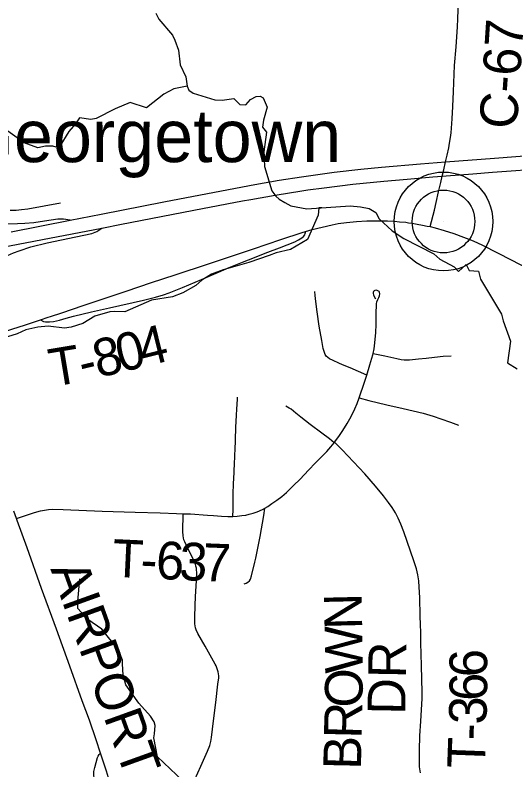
# Model space of a CAD drawing. Extents: x 0 to 34, y 0 to 22.
# Drawn here: x 6.555 to 7.308, y 16.504 to 17.641 of the extents above; entities that cross this region are included whole.
import ezdxf

# ---------------------------------------------------------------- set-up
doc = ezdxf.new("R2010")
doc.units = 0
for name, color, linetype in [('GM_X_County_Road', 7, 'Continuous'), ('GM_X_County_Road_Text', 7, 'Continuous'), ('GM_X_Interchange_Ramps', 7, 'Continuous'), ('GM_X_Interstate_Route', 7, 'Continuous'), ('GM_X_Minor_River', 7, 'Continuous'), ('GM_X_Township_Road', 7, 'Continuous'), ('GM_X_Township_Road_Text', 7, 'Continuous'), ('GM_X_Unincorporated', 7, 'Continuous'), ('GM_X_Unincorporated_Location', 7, 'Continuous'), ('GM_X_Unincorporated_Text', 7, 'Continuous'), ('GM_X_US_Route', 7, 'Continuous')]:
    doc.layers.add(name, color=color, linetype=linetype)

msp = doc.modelspace()

# ---------------------------------------------------------------- linework, layer by layer
at = {"layer": 'GM_X_County_Road'}
msp.add_line((6.5568, 16.8829), (6.5527, 16.8941), dxfattribs=at)
for points in [[(7.1802, 17.3223), (7.1867, 17.3472), (7.1894, 17.3588), (7.1931, 17.3749), (7.1963, 17.3887), (7.1986, 17.3984), (7.2008, 17.4077), (7.2036, 17.4197), (7.206, 17.4299), (7.2083, 17.4409), (7.2096, 17.4482), (7.2111, 17.4564), (7.2119, 17.4638), (7.2134, 17.4847), (7.2144, 17.5034), (7.2154, 17.5259), (7.2173, 17.5649), (7.2198, 17.5933), (7.2216, 17.6233), (7.2223, 17.6353), (7.2228, 17.6488), (7.2227, 17.665)], [(6.6836, 16.5295), (6.677, 16.5496), (6.6667, 16.579), (6.6561, 16.6082), (6.6372, 16.6608), (6.6172, 16.7163), (6.5948, 16.7775), (6.5727, 16.8389), (6.5579, 16.8797), (6.5568, 16.8829)], [(6.7282, 16.3586), (6.7265, 16.3668), (6.7205, 16.3942), (6.7141, 16.4214), (6.704, 16.4605), (6.6968, 16.4875), (6.6924, 16.5024), (6.6836, 16.5295)]]:
    msp.add_lwpolyline(points, dxfattribs=at)
at = {"layer": 'GM_X_Interchange_Ramps'}
for points in [[(6.638, 17.332), (6.6278, 17.3335), (6.6194, 17.3334), (6.5993, 17.3304), (6.5832, 17.3283), (6.5694, 17.327), (6.5585, 17.3265), (6.5368, 17.3262), (6.5244, 17.3268), (6.5151, 17.3271), (6.475, 17.3308), (6.4102, 17.3376), (6.3948, 17.3382), (6.3824, 17.3378), (6.3748, 17.3371), (6.3654, 17.3359), (6.3518, 17.333), (6.3398, 17.3297), (6.3253, 17.3243), (6.3077, 17.3182)], [(6.4063, 17.2039), (6.4286, 17.2158), (6.4804, 17.2447), (6.5267, 17.2707), (6.5435, 17.279), (6.5525, 17.283), (6.5608, 17.2861), (6.5786, 17.292), (6.6029, 17.2981), (6.6461, 17.3071), (6.6703, 17.312), (6.6778, 17.315), (6.6856, 17.3202)]]:
    msp.add_lwpolyline(points, dxfattribs=at)
at = {"layer": 'GM_X_Interstate_Route'}
msp.add_line((7.2045, 17.3988), (7.2449, 17.4019), dxfattribs=at)
for points in [[(7.2036, 17.4197), (7.2772, 17.4256), (7.4507, 17.4388)], [(6.5486, 17.3144), (6.638, 17.332), (6.6845, 17.3411), (6.7789, 17.3595), (6.8552, 17.3741), (6.9162, 17.3858), (6.9529, 17.3921), (6.9867, 17.3973), (7.0359, 17.4041), (7.076, 17.4088), (7.1069, 17.412), (7.1657, 17.4167), (7.2036, 17.4197)], [(7.2449, 17.4019), (7.2745, 17.4042), (7.3581, 17.4105)], [(6.9959, 17.3775), (7.0208, 17.3809), (7.064, 17.3861), (7.1104, 17.391), (7.1455, 17.394)], [(7.1455, 17.394), (7.1846, 17.3973), (7.1986, 17.3984), (7.2045, 17.3988)], [(6.8976, 17.361), (6.9103, 17.3634), (6.947, 17.3699), (6.987, 17.3762), (6.9959, 17.3775)], [(6.4461, 17.2744), (6.5961, 17.303), (6.6856, 17.3202), (6.7151, 17.3259), (6.8371, 17.3495), (6.8976, 17.361)]]:
    msp.add_lwpolyline(points, dxfattribs=at)
at = {"layer": 'GM_X_Minor_River'}
for points in [[(6.767, 17.6438), (6.7716, 17.6347), (6.7918, 17.6105), (6.7956, 17.6029), (6.801, 17.5878), (6.8037, 17.5661), (6.8121, 17.548), (6.8141, 17.5339), (6.8164, 17.5279), (6.8232, 17.5234), (6.8558, 17.5133), (6.8668, 17.5126), (6.8845, 17.5153), (6.8937, 17.5063), (6.9027, 17.5056), (6.9095, 17.5139), (6.9182, 17.5182), (6.9239, 17.5186), (6.9288, 17.5163), (6.9345, 17.5023), (6.9293, 17.4825), (6.9275, 17.4719), (6.9336, 17.4647), (6.9296, 17.4351), (6.9308, 17.4127), (6.9416, 17.3763), (6.9477, 17.368), (6.953, 17.3635), (6.9613, 17.3586), (6.9705, 17.3537), (6.9943, 17.3493), (7.0597, 17.3538), (7.0752, 17.352), (7.0885, 17.3494)], [(6.8141, 17.5339), (6.7941, 17.53), (6.779, 17.5216), (6.753, 17.5013), (6.728, 17.5092), (6.7057, 17.4996), (6.677, 17.485), (6.6691, 17.4834), (6.6517, 17.4864), (6.646, 17.4772), (6.6359, 17.4658), (6.6224, 17.4437), (6.6167, 17.4422), (6.6114, 17.4436), (6.6004, 17.4436), (6.5891, 17.4412), (6.5682, 17.4483), (6.5402, 17.4687)], [(7.0169, 17.3508), (7.0128, 17.3505), (7.0114, 17.3395), (6.9953, 17.303), (6.97, 17.288), (6.9481, 17.283), (6.9379, 17.2791), (6.9073, 17.2683), (6.8684, 17.2575), (6.8507, 17.2506), (6.836, 17.2418), (6.8273, 17.2338), (6.8077, 17.2226), (6.7918, 17.2165), (6.7605, 17.2114), (6.7201, 17.1941), (6.7046, 17.1944), (6.6974, 17.1943), (6.6751, 17.1874), (6.657, 17.1763), (6.6392, 17.1709), (6.629, 17.1697), (6.6048, 17.1726), (6.5889, 17.171), (6.5708, 17.1671), (6.5579, 17.1609), (6.502, 17.1439)], [(7.0885, 17.3494), (7.0984, 17.3438), (7.1037, 17.3343), (7.1231, 17.3162), (7.1405, 17.3045), (7.186, 17.2816), (7.1948, 17.2733), (7.2164, 17.262), (7.2229, 17.2548), (7.2349, 17.2655), (7.2391, 17.2561), (7.2531, 17.2554), (7.2562, 17.2433), (7.2879, 17.1903), (7.2902, 17.1804), (7.3013, 17.1497), (7.2969, 17.1171), (7.3114, 17.108)], [(6.8076, 16.4881), (6.7692, 16.5239), (6.7637, 16.5528), (6.7648, 16.5589), (6.7659, 16.5714), (6.7644, 16.5767), (6.7587, 16.5854), (6.7412, 16.6047), (6.7217, 16.6326), (6.7175, 16.6471), (6.7167, 16.6641), (6.7166, 16.6694), (6.7101, 16.6857), (6.6854, 16.7163), (6.6645, 16.7307), (6.6493, 16.7473), (6.6492, 16.7583), (6.6521, 16.7921)]]:
    msp.add_lwpolyline(points, dxfattribs=at)
at = {"layer": 'GM_X_Township_Road'}
msp.add_line((7.0355, 16.997), (7.036, 16.9976), dxfattribs=at)
for points in [[(6.5472, 17.3473), (6.5562, 17.3473), (6.5644, 17.3479), (6.5742, 17.3493), (6.6231, 17.3582)], [(6.9165, 17.2765), (6.9358, 17.2838), (6.9532, 17.2905), (6.9762, 17.2997), (6.9818, 17.3023), (6.9845, 17.3038), (6.9871, 17.3054), (6.9895, 17.3074), (6.9913, 17.3099), (6.9922, 17.3118), (6.9924, 17.3137), (6.9924, 17.3149)], [(6.6316, 17.1845), (6.6426, 17.1876), (6.6697, 17.1941), (6.6969, 17.2001), (6.7483, 17.2116), (6.7664, 17.2161), (6.7783, 17.2195), (6.787, 17.2225), (6.8071, 17.2308), (6.8356, 17.2429), (6.8612, 17.2538), (6.8776, 17.2607), (6.8974, 17.269), (6.9155, 17.2761), (6.9165, 17.2765)], [(7.0847, 17.0987), (7.0599, 17.1096), (7.0484, 17.1145), (7.0427, 17.1168), (7.0341, 17.1206), (7.0285, 17.1234), (7.0259, 17.1252), (7.0237, 17.1273), (7.0221, 17.1299), (7.021, 17.1328), (7.0193, 17.1389), (7.0169, 17.1511), (7.0131, 17.1725), (7.0099, 17.194), (7.0081, 17.2094), (7.007, 17.2187), (7.0064, 17.2249)], [(7.0943, 17.1315), (7.0958, 17.1383), (7.0971, 17.1475), (7.0984, 17.1629), (7.099, 17.1752), (7.0992, 17.1938), (7.0994, 17.2032), (7.0996, 17.2063), (7.1002, 17.2093), (7.1013, 17.2125), (7.1031, 17.2154), (7.1042, 17.2182), (7.1044, 17.221), (7.1039, 17.2236), (7.1033, 17.2247), (7.1026, 17.2254), (7.1007, 17.2262), (7.099, 17.2265), (7.0971, 17.2263), (7.0959, 17.2257), (7.0952, 17.2249), (7.0947, 17.2234), (7.0944, 17.2215), (7.0948, 17.2197), (7.0958, 17.2173), (7.0981, 17.2135)], [(6.593, 17.1821), (6.5975, 17.1797), (6.6004, 17.179), (6.6034, 17.1788), (6.6065, 17.1789), (6.6126, 17.1797), (6.6217, 17.1817), (6.6316, 17.1845)], [(7.0847, 17.0987), (7.0897, 17.1144), (7.0939, 17.1293), (7.0943, 17.1315)], [(7.0943, 17.1315), (7.1122, 17.1276), (7.13, 17.1236), (7.1367, 17.1224), (7.1411, 17.1219), (7.1494, 17.122), (7.1627, 17.1231), (7.1745, 17.1244), (7.1871, 17.1256), (7.2001, 17.1272), (7.2121, 17.1279)], [(7.0735, 17.0644), (7.0814, 17.0882), (7.0847, 17.0987)], [(6.8828, 16.886), (6.8834, 16.8962), (6.8835, 16.92), (6.884, 16.935), (6.8849, 16.9523), (6.8857, 16.9677), (6.8861, 16.9739), (6.8862, 16.98), (6.8863, 16.986), (6.8868, 17.0013), (6.8877, 17.0198), (6.8886, 17.0383), (6.889, 17.0475), (6.8899, 17.0628), (6.8901, 17.0658)], [(7.036, 16.9976), (7.0383, 17.0004), (7.0437, 17.0077), (7.0489, 17.0153), (7.0553, 17.0259), (7.0613, 17.0367), (7.0667, 17.0478), (7.0705, 17.0562), (7.0735, 17.0644)], [(7.0735, 17.0644), (7.0877, 17.0605), (7.1152, 17.0542), (7.1395, 17.0486), (7.1698, 17.0413), (7.1848, 17.0371), (7.1966, 17.0332), (7.2112, 17.0278), (7.2229, 17.0232)], [(7.0355, 16.997), (7.0285, 17.003), (7.0169, 17.0116), (6.9997, 17.0242), (6.9853, 17.0356), (6.9781, 17.0416), (6.9746, 17.0444), (6.9707, 17.0475), (6.968, 17.0491), (6.9653, 17.0507), (6.9626, 17.0522)], [(6.9312, 16.8985), (6.9358, 16.9011), (6.9419, 16.9054), (6.9495, 16.9106), (6.9569, 16.9161), (6.9639, 16.9222), (6.975, 16.9329), (6.9837, 16.9417), (6.9975, 16.9561), (7.0071, 16.9664), (7.018, 16.9773), (7.0244, 16.984), (7.0305, 16.9909), (7.0355, 16.997)], [(7.1657, 16.4999), (7.1644, 16.5091), (7.1641, 16.5154), (7.1641, 16.534), (7.1649, 16.5558), (7.1661, 16.5776), (7.1681, 16.6117), (7.1682, 16.621), (7.1671, 16.6614), (7.1665, 16.6956), (7.1663, 16.7111), (7.1659, 16.7235), (7.1655, 16.7359), (7.1648, 16.7639), (7.164, 16.7795), (7.1632, 16.7888), (7.1618, 16.798), (7.1596, 16.8071), (7.1559, 16.819), (7.1405, 16.863), (7.136, 16.8746), (7.1322, 16.8832), (7.1279, 16.8914), (7.123, 16.8994), (7.1177, 16.9071), (7.1102, 16.917), (7.0982, 16.9314), (7.0818, 16.9501), (7.065, 16.9684), (7.0478, 16.9863), (7.036, 16.9976)], [(6.5568, 16.8829), (6.5839, 16.8917), (6.5929, 16.8943), (6.599, 16.8956), (6.6053, 16.8964), (6.6116, 16.8967), (6.6272, 16.8964), (6.6862, 16.8941), (6.7359, 16.8926), (6.7732, 16.8915), (6.7981, 16.8906), (6.8079, 16.8901)], [(6.8256, 16.4901), (6.8345, 16.5099), (6.8446, 16.5326), (6.8481, 16.5413), (6.8499, 16.5472), (6.8509, 16.5533), (6.854, 16.578), (6.8573, 16.6058), (6.8605, 16.6336), (6.8616, 16.6428), (6.8616, 16.6459), (6.8607, 16.6521), (6.8599, 16.6551), (6.859, 16.6581), (6.8579, 16.661), (6.8565, 16.6637), (6.841, 16.6907), (6.8304, 16.7097), (6.8279, 16.7154), (6.8268, 16.7183), (6.8261, 16.7213), (6.8257, 16.7244), (6.8255, 16.7275), (6.8257, 16.7337), (6.8264, 16.7524), (6.8269, 16.7648), (6.828, 16.7896), (6.8285, 16.8021), (6.8284, 16.8052), (6.828, 16.8083), (6.8274, 16.8113), (6.8266, 16.8143), (6.8255, 16.8172), (6.8242, 16.82), (6.8143, 16.8395), (6.8104, 16.8479), (6.8093, 16.8508), (6.8085, 16.8538), (6.8079, 16.8569), (6.8074, 16.8631), (6.8079, 16.8901)], [(6.8079, 16.8901), (6.8191, 16.8897), (6.8446, 16.8879), (6.8538, 16.8873), (6.8661, 16.8865), (6.8754, 16.8861), (6.8828, 16.886)], [(6.8828, 16.886), (6.8894, 16.8863), (6.8965, 16.8872), (6.9027, 16.8881), (6.9075, 16.8892), (6.9134, 16.8909), (6.9194, 16.893), (6.9275, 16.8965), (6.9312, 16.8985)], [(6.9002, 16.7845), (6.903, 16.7855), (6.9058, 16.787), (6.9082, 16.7889), (6.9098, 16.7913), (6.9111, 16.7966), (6.916, 16.8171), (6.9174, 16.8231), (6.9242, 16.8558), (6.9295, 16.8872), (6.9312, 16.8985)], [(6.6785, 16.4742), (6.6775, 16.478), (6.6746, 16.49), (6.6734, 16.496), (6.6732, 16.4991), (6.6734, 16.5021), (6.6749, 16.5081), (6.6792, 16.5228), (6.6802, 16.5251), (6.6816, 16.5274), (6.6836, 16.5295)]]:
    msp.add_lwpolyline(points, dxfattribs=at)
at = {"layer": 'GM_X_Unincorporated'}
for radius in [0.0744, 0.0472]:
    msp.add_circle((7.2005, 17.3301), radius, dxfattribs=at)
at = {"layer": 'GM_X_Unincorporated_Location'}
msp.add_line((7.2005, 17.3301), (7.2005, 17.3301), dxfattribs=at)
at = {"layer": 'GM_X_US_Route'}
for points in [[(6.9924, 17.3149), (7.0026, 17.3178), (7.0176, 17.3217), (7.0327, 17.3252), (7.0418, 17.3269), (7.0541, 17.3285), (7.0695, 17.33), (7.085, 17.3309), (7.0927, 17.3311)], [(7.0927, 17.3311), (7.1005, 17.3312), (7.116, 17.331), (7.1264, 17.3304), (7.1343, 17.3298), (7.1436, 17.3289), (7.1478, 17.3283)], [(7.1478, 17.3283), (7.1531, 17.3275), (7.1606, 17.3262), (7.1686, 17.3248), (7.1759, 17.3232), (7.1802, 17.3223)], [(7.1802, 17.3223), (7.1878, 17.3204), (7.2014, 17.3165), (7.2162, 17.3119), (7.2308, 17.3067), (7.2452, 17.3008), (7.2592, 17.2943), (7.3035, 17.2717), (7.3255, 17.2603), (7.3449, 17.2503), (7.356, 17.2448), (7.3739, 17.2355), (7.3864, 17.2293), (7.3977, 17.2241), (7.405, 17.221)], [(6.6081, 17.1871), (6.625, 17.1928), (6.6574, 17.2036), (6.7223, 17.2254), (6.7606, 17.238), (6.796, 17.2499), (6.8461, 17.2665), (6.914, 17.289), (6.9552, 17.303), (6.9877, 17.3135), (6.9924, 17.3149)], [(6.593, 17.1821), (6.6044, 17.1858), (6.6081, 17.1871)], [(6.4809, 17.1449), (6.5513, 17.1683), (6.5689, 17.1742), (6.593, 17.1821)]]:
    msp.add_lwpolyline(points, dxfattribs=at)

# ---------------------------------------------------------------- texts
at = {"layer": 'GM_X_County_Road_Text'}
for s, rotation, p in [('C-67', 86.2797, (7.311, 17.4683)), ('AIRPORT', 289.8051, (6.6077, 16.8071))]:
    msp.add_text(s, height=0.05682, rotation=rotation, dxfattribs=at).set_placement(p)
at = {"layer": 'GM_X_Township_Road_Text'}
for s, height, rotation, p in [('4', 0.0568, 13.9582, (6.7483, 17.1109)), ('0', 0.0568, 13.5981, (6.7139, 17.1026)), ('8', 0.0568, 13.5627, (6.6798, 17.0944)), ('T', 0.0568, 9.4109, (6.6108, 17.0811)), ('-', 0.0568, 13.4574, (6.657, 17.0889)), ('T', 0.0568, 357.3334, (6.7004, 16.7952)), ('6', 0.0568, 357.3548, (6.7662, 16.7921)), ('3', 0.0568, 357.4376, (6.8013, 16.7905)), ('7', 0.0568, 357.8518, (6.8367, 16.7889)), ('-', 0.0568, 357.3294, (6.7429, 16.7932)), ('N', 0.0568, 91.3464, (7.0781, 16.7163)), ('W', 0.0568, 90.8357, (7.079, 16.6499)), ('DR', 0.05682, 89.0143, (7.1427, 16.5872)), ('6', 0.0568, 90.4167, (7.2665, 16.6443)), ('O', 0.0568, 88.7914, (7.078, 16.5977)), ('6', 0.0568, 89.2512, (7.2661, 16.6081)), ('3', 0.0568, 88.5087, (7.2651, 16.5723)), ('R', 0.0568, 88.7861, (7.077, 16.5511)), ('-', 0.0568, 88.0219, (7.2643, 16.5484)), ('B', 0.0568, 88.79, (7.076, 16.5044)), ('T', 0.0568, 87.8867, (7.2627, 16.5058))]:
    msp.add_text(s, height=height, rotation=rotation, dxfattribs=at).set_placement(p)
at = {"layer": 'GM_X_Unincorporated_Text'}
msp.add_text('Georgetown', height=0.07898, rotation=0, dxfattribs=at).set_placement((6.4709, 17.4195))

doc.saveas('drawing.dxf')
